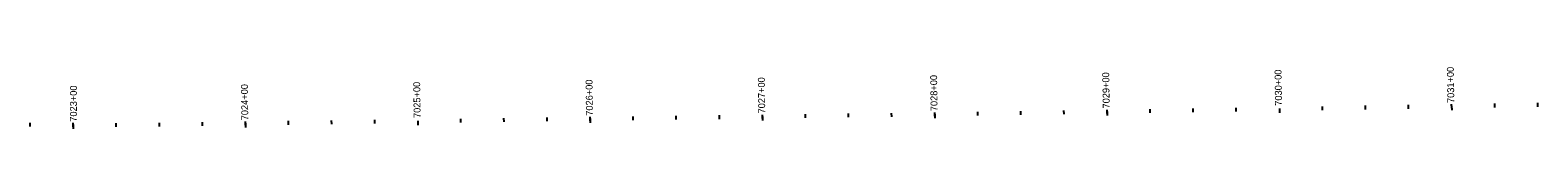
# Model space of a CAD drawing. Extents: x 5195296 to 5198948, y 3709168 to 3709552.
# Drawn here: x 5198073 to 5198948, y 3709347 to 3709382 of the extents above; entities that cross this region are included whole.
import ezdxf

# ---------------------------------------------------------------- set-up
doc = ezdxf.new("R2010")
doc.units = 0
doc.layers.add('dsnAlignmentStation', color=7, linetype='Continuous')
doc.layers.add('dsnProfileEntranceGradeProp', color=7, linetype='Continuous')

msp = doc.modelspace()

# ---------------------------------------------------------------- linework, layer by layer
at = {"layer": 'dsnAlignmentStation'}
for p, q in [((5198872.76, 3709358.28), (5198872.72, 3709360.47)), ((5198922.75, 3709359.07), (5198922.72, 3709361.26)), ((5198947.75, 3709359.47), (5198947.71, 3709361.65)), ((5198247.82, 3709349.32), (5198247.79, 3709351.5)), ((5198272.82, 3709349.65), (5198272.79, 3709351.83)), ((5198322.81, 3709350.31), (5198322.79, 3709352.49)), ((5198347.81, 3709350.64), (5198347.78, 3709352.83)), ((5198372.81, 3709350.97), (5198372.78, 3709353.16)), ((5198397.79, 3709352.53), (5198397.82, 3709350.08)), ((5198422.81, 3709351.63), (5198422.78, 3709353.82)), ((5198447.8, 3709351.96), (5198447.77, 3709354.15)), ((5198472.8, 3709352.29), (5198472.77, 3709354.48)), ((5198497.78, 3709353.85), (5198497.82, 3709351.4)), ((5198522.8, 3709352.96), (5198522.77, 3709355.14)), ((5198547.8, 3709353.29), (5198547.77, 3709355.47)), ((5198572.79, 3709353.62), (5198572.76, 3709355.8)), ((5198597.77, 3709355.17), (5198597.81, 3709352.72)), ((5198622.79, 3709354.32), (5198622.75, 3709356.5)), ((5198647.78, 3709354.72), (5198647.75, 3709356.9)), ((5198672.78, 3709355.11), (5198672.75, 3709357.3)), ((5198697.76, 3709356.73), (5198697.8, 3709354.28)), ((5198722.78, 3709355.9), (5198722.74, 3709358.09)), ((5198747.77, 3709356.3), (5198747.74, 3709358.48)), ((5198772.77, 3709356.7), (5198772.73, 3709358.88)), ((5198797.75, 3709358.32), (5198797.79, 3709355.87)), ((5198822.76, 3709357.49), (5198822.73, 3709359.67)), ((5198847.76, 3709357.89), (5198847.73, 3709360.07)), ((5198897.73, 3709359.9), (5198897.77, 3709357.45)), ((5198072.83, 3709347.9), (5198072.84, 3709350.09)), ((5198097.84, 3709349.06), (5198097.83, 3709346.61)), ((5198122.83, 3709347.76), (5198122.84, 3709349.94)), ((5198147.83, 3709348), (5198147.8, 3709350.18)), ((5198172.83, 3709348.33), (5198172.8, 3709350.51)), ((5198197.81, 3709349.88), (5198197.84, 3709347.43)), ((5198222.82, 3709348.99), (5198222.79, 3709351.17)), ((5198297.8, 3709351.2), (5198297.83, 3709348.76))]:
    msp.add_line(p, q, dxfattribs=at)
at = {"layer": 'dsnProfileEntranceGradeProp'}
for p, q in [((5198897.75, 3709358.68), (5198897.72, 3709360.86)), ((5198397.81, 3709351.3), (5198397.78, 3709353.49)), ((5198497.8, 3709352.62), (5198497.77, 3709354.81)), ((5198597.79, 3709353.95), (5198597.76, 3709356.13)), ((5198697.78, 3709355.51), (5198697.74, 3709357.69)), ((5198797.75, 3709358.32), (5198797.79, 3709355.87)), ((5198097.83, 3709347.83), (5198097.84, 3709350.02)), ((5198197.83, 3709348.66), (5198197.8, 3709350.84)), ((5198297.8, 3709351.2), (5198297.83, 3709348.76))]:
    msp.add_line(p, q, dxfattribs=at)

# ---------------------------------------------------------------- texts
at = {"layer": 'dsnAlignmentStation'}
for s, rotation, p in [('7029+00', 90.90825, (5198699.31, 3709358.45)), ('7030+00', 90.90825, (5198799.29, 3709360.03)), ('7031+00', 90.90825, (5198899.28, 3709361.62)), ('7023+00', 89.83445, (5198099.92, 3709350.74)), ('7024+00', 90.75752, (5198199.43, 3709351.59)), ('7025+00', 90.75752, (5198299.42, 3709352.92)), ('7026+00', 90.75752, (5198399.42, 3709354.24)), ('7027+00', 90.75752, (5198499.41, 3709355.56)), ('7028+00', 90.75752, (5198599.4, 3709356.88))]:
    msp.add_text(s, height=4.008, rotation=rotation, dxfattribs=at).set_placement(p)
at = {"layer": 'dsnProfileEntranceGradeProp'}
for s, rotation, p in [('7030+00', 90.90825, (5198799.29, 3709360.03)), ('7025+00', 90.75752, (5198299.42, 3709352.92))]:
    msp.add_text(s, height=4.008, rotation=rotation, dxfattribs=at).set_placement(p)

doc.saveas('drawing.dxf')
